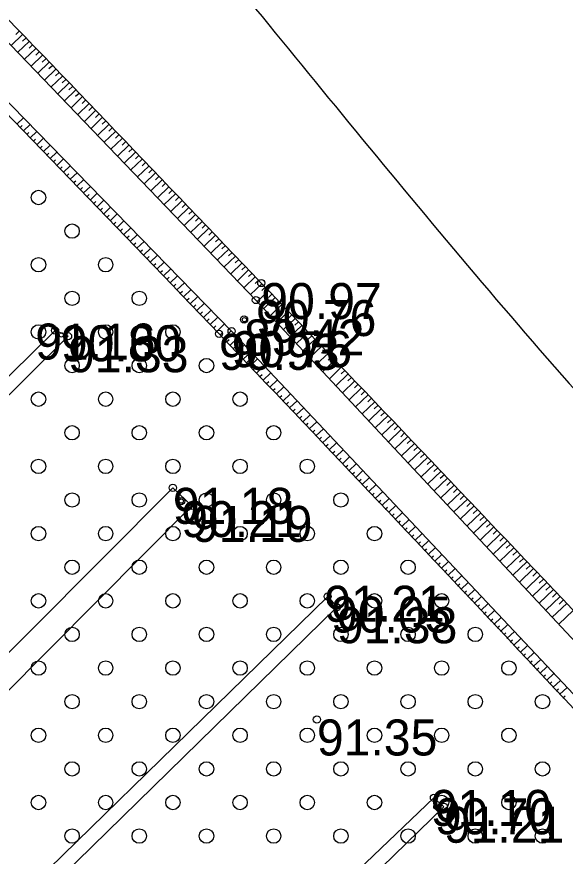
# Model space of a CAD drawing. Extents: x 316000 to 728450, y 314368 to 726000.
# Drawn here: x 725911.7 to 725968.9, y 315372.4 to 315459.8 of the extents above; entities that cross this region are included whole.
import ezdxf

# ---------------------------------------------------------------- set-up
doc = ezdxf.new("R2010")
doc.units = 0
for name, color, linetype in [('HIDG_ELEM_####_####_#', 7, 'Continuous'), ('HIDG_GRAV_####_####_#', 7, 'Continuous'), ('RELJ_AATZ_####_TKST_#', 7, 'Continuous'), ('RELJ_ELEM_####_####_#', 7, 'Continuous'), ('RELJ_HORZ_PAMT_####_#', 7, 'Continuous'), ('RELJ_NOGA_####_####_#', 7, 'Continuous'), ('TERT_ELEM_####_####_#', 7, 'Continuous')]:
    doc.layers.add(name, color=color, linetype=linetype)

msp = doc.modelspace()

# ---------------------------------------------------------------- linework, layer by layer
at = {"layer": 'HIDG_ELEM_####_####_#'}
for centre in [(725935.445, 315428.263), (725916.379, 315426.689), (725928.87, 315409.384), (725944.376, 315398.824), (725955.39, 315377.546)]:
    msp.add_circle(centre, 0.225, dxfattribs=at)
at = {"layer": 'HIDG_GRAV_####_####_#'}
for points in [[(726259.175, 315086.515), (726260.768, 315088.859), (726179.005, 315175.766), (726127.859, 315229.056), (726063.055, 315296.073), (725998.338, 315364.317), (725936.648, 315430.32), (725875.345, 315494.083), (725809.436, 315562.192), (725743.944, 315631.872)], [(725741.161, 315628.109), (725806.062, 315558.993), (725870.895, 315491.871), (725934.12, 315427.077), (725995.775, 315361.632), (726059.846, 315293.396), (726126.03, 315226.728), (726194.491, 315154.86), (726259.175, 315086.515)], [(725738.04, 315252.213), (725739.749, 315250.831), (725917.078, 315426.552), (725915.721, 315427.141), (725738.04, 315252.213)], [(725927.989, 315410.766), (725929.989, 315408.885), (725850.785, 315329.182), (725850.792, 315329.17), (725757.22, 315237.636), (725756.413, 315238.371), (725756.347, 315238.429), (725927.989, 315410.766)], [(725944.123, 315399.451), (725945.082, 315398.332), (725768.124, 315225.339), (725766.926, 315226.564), (725944.123, 315399.451)], [(725955.193, 315378.49), (725956.226, 315377.559), (725782.603, 315208.688), (725780.552, 315211.672), (725955.193, 315378.49)]]:
    msp.add_lwpolyline(points, dxfattribs=at)
at = {"layer": 'RELJ_ELEM_####_####_#'}
for centre in [(725937.206, 315432.091), (725936.648, 315430.32), (725935.41, 315428.298), (725915.721, 315427.141), (725934.12, 315427.077), (725917.078, 315426.552), (725932.803, 315426.796), (725927.989, 315410.766), (725928.87, 315409.384), (725929.989, 315408.885), (725944.123, 315399.451), (725945.082, 315398.332), (725943, 315386.643), (725955.193, 315378.49), (725956.226, 315377.559)]:
    msp.add_circle(centre, 0.375, dxfattribs=at)
at = {"layer": 'RELJ_HORZ_PAMT_####_#'}
msp.add_spline([(726116.344, 315699.088), (726105.94, 315702.687), (726040.128, 315715), (725990.823, 315710.424), (725942.032, 315708.248), (725920.28, 315706.773), (725880.366, 315714.514), (725859.054, 315708.681), (725859.054, 315672.662), (725851.263, 315613.969), (725853.471, 315568.895), (725840.997, 315555.788), (725885.558, 315509.629), (725935.943, 315461.491), (725983.423, 315406.25), (726032.861, 315360.511), (726082.852, 315311.191), (726122.235, 315248.757), (726137.049, 315229.286), (726180.187, 315183.1), (726194.517, 315168.27), (726211.91, 315146.926), (726212.513, 315143.157)], degree=3, dxfattribs=at)
at = {"layer": 'RELJ_NOGA_####_####_#'}
for p, q in [((725911.974, 315458.323), (725911.624, 315457.986)), ((725912.321, 315457.963), (725911.153, 315456.838)), ((725913.015, 315457.243), (725911.846, 315456.117)), ((725912.668, 315457.603), (725912.318, 315457.266)), ((725913.709, 315456.523), (725912.539, 315455.396)), ((725913.362, 315456.883), (725913.011, 315456.545)), ((725914.403, 315455.803), (725913.232, 315454.675)), ((725914.056, 315456.163), (725913.705, 315455.825)), ((725914.75, 315455.443), (725914.399, 315455.105)), ((725915.097, 315455.083), (725913.925, 315453.955)), ((725915.444, 315454.723), (725915.092, 315454.384)), ((725915.791, 315454.363), (725914.618, 315453.234)), ((725916.137, 315454.003), (725915.786, 315453.664)), ((725916.484, 315453.643), (725915.311, 315452.513)), ((725917.178, 315452.923), (725916.004, 315451.792)), ((725916.831, 315453.283), (725916.479, 315452.944)), ((725917.872, 315452.202), (725916.697, 315451.071)), ((725917.525, 315452.562), (725917.173, 315452.223)), ((725918.565, 315451.482), (725917.39, 315450.35)), ((725918.219, 315451.842), (725917.866, 315451.503)), ((725918.912, 315451.122), (725918.56, 315450.782)), ((725919.259, 315450.762), (725918.083, 315449.63)), ((725919.606, 315450.402), (725919.253, 315450.062)), ((725911.748, 315448.652), (725912.426, 315449.31)), ((725919.953, 315450.041), (725918.776, 315448.909)), ((725920.646, 315449.321), (725919.469, 315448.188)), ((725920.299, 315449.681), (725919.946, 315449.341)), ((725912.097, 315448.293), (725912.3, 315448.491)), ((725912.445, 315447.934), (725913.124, 315448.594)), ((725921.34, 315448.6), (725920.162, 315447.467)), ((725920.993, 315448.961), (725920.64, 315448.621)), ((725912.793, 315447.576), (725912.997, 315447.774)), ((725913.141, 315447.217), (725913.823, 315447.878)), ((725922.033, 315447.88), (725920.855, 315446.747)), ((725921.686, 315448.24), (725921.333, 315447.9)), ((725913.489, 315446.858), (725913.694, 315447.056)), ((725913.837, 315446.499), (725914.521, 315447.162)), ((725922.727, 315447.159), (725921.548, 315446.026)), ((725922.38, 315447.52), (725922.026, 315447.18)), ((725923.073, 315446.799), (725922.72, 315446.459)), ((725914.185, 315446.14), (725914.391, 315446.339)), ((725914.533, 315445.781), (725915.22, 315446.446)), ((725923.42, 315446.439), (725922.241, 315445.305)), ((725923.767, 315446.079), (725923.413, 315445.738)), ((725914.881, 315445.421), (725915.087, 315445.621)), ((725915.229, 315445.062), (725915.918, 315445.73)), ((725915.924, 315444.344), (725916.617, 315445.014)), ((725924.113, 315445.718), (725922.934, 315444.584)), ((725924.807, 315444.998), (725923.627, 315443.863)), ((725924.46, 315445.358), (725924.106, 315445.018)), ((725915.577, 315444.703), (725915.784, 315444.904)), ((725916.272, 315443.985), (725916.48, 315444.186)), ((725916.62, 315443.625), (725917.315, 315444.299)), ((725925.5, 315444.277), (725924.32, 315443.143)), ((725925.153, 315444.637), (725924.799, 315444.297)), ((725916.968, 315443.266), (725917.177, 315443.468)), ((725917.315, 315442.907), (725918.014, 315443.583)), ((725926.193, 315443.556), (725925.013, 315442.422)), ((725925.846, 315443.916), (725925.492, 315443.576)), ((725926.539, 315443.196), (725926.186, 315442.855)), ((725917.663, 315442.547), (725917.873, 315442.751)), ((725918.01, 315442.188), (725918.713, 315442.867)), ((725926.886, 315442.835), (725925.706, 315441.701)), ((725927.233, 315442.475), (725926.879, 315442.134)), ((725918.358, 315441.828), (725918.569, 315442.032)), ((725918.705, 315441.469), (725919.411, 315442.151)), ((725927.579, 315442.114), (725926.399, 315440.98)), ((725927.926, 315441.754), (725927.572, 315441.414)), ((725919.053, 315441.109), (725919.265, 315441.314)), ((725919.4, 315440.75), (725920.11, 315441.435)), ((725919.748, 315440.39), (725919.961, 315440.596)), ((725920.095, 315440.03), (725920.808, 315440.719)), ((725928.272, 315441.394), (725927.092, 315440.259)), ((725928.965, 315440.673), (725927.785, 315439.538)), ((725928.619, 315441.033), (725928.265, 315440.693)), ((725920.442, 315439.67), (725920.657, 315439.878)), ((725920.789, 315439.311), (725921.507, 315440.003)), ((725929.658, 315439.952), (725928.478, 315438.818)), ((725929.312, 315440.312), (725928.958, 315439.972)), ((725921.136, 315438.951), (725921.352, 315439.159)), ((725921.484, 315438.591), (725922.206, 315439.287)), ((725930.351, 315439.231), (725929.171, 315438.097)), ((725930.005, 315439.591), (725929.651, 315439.251)), ((725930.697, 315438.87), (725930.344, 315438.53)), ((725921.831, 315438.231), (725922.048, 315438.44)), ((725922.178, 315437.871), (725922.904, 315438.571)), ((725931.044, 315438.509), (725929.864, 315437.376)), ((725931.39, 315438.149), (725931.036, 315437.809)), ((725922.525, 315437.511), (725922.743, 315437.722)), ((725922.872, 315437.151), (725923.603, 315437.855)), ((725923.565, 315436.431), (725924.301, 315437.139)), ((725931.737, 315437.788), (725930.557, 315436.655)), ((725932.429, 315437.067), (725931.25, 315435.935)), ((725932.083, 315437.428), (725931.729, 315437.088)), ((725923.218, 315436.791), (725923.438, 315437.003)), ((725923.912, 315436.071), (725924.134, 315436.284)), ((725924.259, 315435.71), (725925, 315436.423)), ((725933.122, 315436.346), (725931.943, 315435.214)), ((725932.776, 315436.706), (725932.422, 315436.367)), ((725924.605, 315435.35), (725924.828, 315435.565)), ((725924.952, 315434.99), (725925.698, 315435.708)), ((725933.815, 315435.625), (725932.636, 315434.493)), ((725933.468, 315435.985), (725933.115, 315435.646)), ((725925.299, 315434.629), (725925.523, 315434.845)), ((725925.645, 315434.269), (725926.397, 315434.992)), ((725934.507, 315434.903), (725933.329, 315433.772)), ((725934.161, 315435.264), (725933.807, 315434.924)), ((725934.853, 315434.542), (725934.5, 315434.203)), ((725925.992, 315433.908), (725926.218, 315434.126)), ((725926.338, 315433.548), (725927.096, 315434.276)), ((725935.2, 315434.182), (725934.022, 315433.051)), ((725935.546, 315433.821), (725935.193, 315433.482)), ((725926.684, 315433.187), (725926.912, 315433.406)), ((725927.03, 315432.826), (725927.795, 315433.559)), ((725927.723, 315432.105), (725928.493, 315432.844)), ((725935.892, 315433.46), (725934.715, 315432.331)), ((725936.584, 315432.739), (725935.408, 315431.61)), ((725936.238, 315433.099), (725935.885, 315432.761)), ((725927.377, 315432.465), (725927.607, 315432.686)), ((725928.069, 315431.744), (725928.301, 315431.966)), ((725928.415, 315431.383), (725929.192, 315432.127)), ((725937.277, 315432.017), (725936.101, 315430.889)), ((725936.931, 315432.378), (725936.578, 315432.039)), ((725928.761, 315431.022), (725928.995, 315431.246)), ((725929.107, 315430.661), (725929.89, 315431.412)), ((725937.969, 315431.295), (725936.792, 315430.166)), ((725937.623, 315431.656), (725937.27, 315431.318)), ((725929.453, 315430.3), (725929.689, 315430.526)), ((725929.799, 315429.939), (725930.589, 315430.696)), ((725938.661, 315430.574), (725937.475, 315429.436)), ((725938.315, 315430.934), (725937.96, 315430.594)), ((725939.007, 315430.213), (725938.65, 315429.87)), ((725930.144, 315429.578), (725930.383, 315429.806)), ((725930.49, 315429.216), (725931.288, 315429.979)), ((725931.181, 315428.494), (725931.986, 315429.264)), ((725939.353, 315429.852), (725938.157, 315428.706)), ((725939.699, 315429.491), (725939.339, 315429.146)), ((725930.836, 315428.855), (725931.076, 315429.085)), ((725931.527, 315428.132), (725931.769, 315428.364)), ((725931.872, 315427.771), (725932.685, 315428.547)), ((725940.045, 315429.13), (725938.84, 315427.975)), ((725940.737, 315428.408), (725939.523, 315427.244)), ((725940.391, 315428.769), (725940.028, 315428.421)), ((725932.217, 315427.409), (725932.463, 315427.643)), ((725932.563, 315427.048), (725933.384, 315427.832)), ((725941.429, 315427.685), (725940.205, 315426.514)), ((725941.083, 315428.047), (725940.717, 315427.696)), ((725932.908, 315426.686), (725933.156, 315426.922)), ((725933.253, 315426.324), (725934.083, 315427.115)), ((725942.12, 315426.963), (725940.888, 315425.783)), ((725941.774, 315427.324), (725941.406, 315426.972)), ((725942.466, 315426.602), (725942.095, 315426.247)), ((725933.598, 315425.962), (725933.847, 315426.199)), ((725933.943, 315425.601), (725934.769, 315426.388)), ((725942.812, 315426.241), (725941.571, 315425.053)), ((725943.157, 315425.879), (725942.784, 315425.522)), ((725934.288, 315425.239), (725934.536, 315425.474)), ((725934.633, 315424.877), (725935.455, 315425.66)), ((725935.323, 315424.153), (725936.141, 315424.932)), ((725943.503, 315425.518), (725942.254, 315424.323)), ((725943.849, 315425.157), (725943.472, 315424.797)), ((725934.978, 315424.515), (725935.224, 315424.749)), ((725935.668, 315423.791), (725935.913, 315424.024)), ((725936.013, 315423.429), (725936.827, 315424.204)), ((725944.194, 315424.796), (725942.936, 315423.592)), ((725944.885, 315424.073), (725943.619, 315422.862)), ((725944.54, 315424.434), (725944.161, 315424.072)), ((725936.358, 315423.067), (725936.601, 315423.298)), ((725936.702, 315422.704), (725937.513, 315423.476)), ((725945.576, 315423.35), (725944.302, 315422.131)), ((725945.231, 315423.711), (725944.85, 315423.347)), ((725937.047, 315422.342), (725937.29, 315422.573)), ((725937.392, 315421.98), (725938.199, 315422.748)), ((725946.267, 315422.627), (725944.984, 315421.401)), ((725945.922, 315422.989), (725945.538, 315422.622)), ((725946.613, 315422.266), (725946.227, 315421.897)), ((725937.736, 315421.618), (725937.978, 315421.847)), ((725938.081, 315421.255), (725938.885, 315422.019)), ((725946.958, 315421.904), (725945.667, 315420.67)), ((725947.304, 315421.543), (725946.915, 315421.171)), ((725938.425, 315420.893), (725938.666, 315421.122)), ((725938.77, 315420.53), (725939.57, 315421.292)), ((725939.459, 315419.806), (725940.257, 315420.563)), ((725947.649, 315421.181), (725946.35, 315419.94)), ((725948.34, 315420.458), (725947.032, 315419.21)), ((725947.994, 315420.82), (725947.603, 315420.446)), ((725939.114, 315420.168), (725939.354, 315420.396)), ((725939.803, 315419.443), (725940.042, 315419.67)), ((725940.147, 315419.08), (725940.942, 315419.835)), ((725949.03, 315419.735), (725947.715, 315418.479)), ((725948.685, 315420.096), (725948.292, 315419.721)), ((725940.491, 315418.718), (725940.73, 315418.944)), ((725940.836, 315418.355), (725941.628, 315419.107)), ((725949.721, 315419.011), (725948.398, 315417.749)), ((725949.376, 315419.373), (725948.98, 315418.995)), ((725941.18, 315417.992), (725941.417, 315418.218)), ((725941.524, 315417.63), (725942.314, 315418.379)), ((725950.411, 315418.288), (725949.08, 315417.018)), ((725950.066, 315418.65), (725949.668, 315418.27)), ((725950.756, 315417.926), (725950.356, 315417.544)), ((725941.868, 315417.267), (725942.105, 315417.491)), ((725942.212, 315416.904), (725943, 315417.651)), ((725951.102, 315417.564), (725949.763, 315416.288)), ((725951.447, 315417.203), (725951.044, 315416.819)), ((725942.556, 315416.541), (725942.792, 315416.765)), ((725942.9, 315416.178), (725943.686, 315416.923)), ((725943.588, 315415.453), (725944.372, 315416.195)), ((725951.792, 315416.841), (725950.446, 315415.557)), ((725952.482, 315416.117), (725951.128, 315414.827)), ((725952.137, 315416.479), (725951.732, 315416.093)), ((725943.244, 315415.815), (725943.479, 315416.039)), ((725943.932, 315415.09), (725944.167, 315415.312)), ((725944.276, 315414.727), (725945.057, 315415.467)), ((725953.172, 315415.393), (725951.811, 315414.097)), ((725952.827, 315415.755), (725952.42, 315415.367)), ((725944.62, 315414.364), (725944.854, 315414.585)), ((725944.963, 315414), (725945.743, 315414.739)), ((725953.862, 315414.67), (725952.494, 315413.366)), ((725953.517, 315415.031), (725953.108, 315414.641)), ((725945.307, 315413.637), (725945.541, 315413.859)), ((725945.651, 315413.274), (725946.429, 315414.011)), ((725954.552, 315413.946), (725953.177, 315412.636)), ((725954.207, 315414.308), (725953.795, 315413.916)), ((725954.897, 315413.584), (725954.483, 315413.19)), ((725945.994, 315412.911), (725946.228, 315413.132)), ((725946.338, 315412.548), (725947.115, 315413.283)), ((725955.241, 315413.222), (725953.859, 315411.905)), ((725955.586, 315412.86), (725955.171, 315412.464)), ((725946.682, 315412.185), (725946.915, 315412.405)), ((725947.025, 315411.821), (725947.801, 315412.555)), ((725947.712, 315411.095), (725948.487, 315411.827)), ((725955.931, 315412.497), (725954.542, 315411.175)), ((725956.621, 315411.773), (725955.225, 315410.444)), ((725956.276, 315412.135), (725955.858, 315411.738)), ((725947.369, 315411.458), (725947.601, 315411.678)), ((725948.056, 315410.731), (725948.288, 315410.951)), ((725948.399, 315410.368), (725949.173, 315411.099)), ((725957.31, 315411.049), (725955.908, 315409.714)), ((725956.966, 315411.411), (725956.546, 315411.012)), ((725948.743, 315410.005), (725948.974, 315410.224)), ((725949.086, 315409.641), (725949.859, 315410.371)), ((725958, 315410.325), (725956.59, 315408.983)), ((725957.655, 315410.687), (725957.233, 315410.285)), ((725949.429, 315409.278), (725949.661, 315409.496)), ((725949.773, 315408.914), (725950.544, 315409.643)), ((725958.689, 315409.6), (725957.273, 315408.253)), ((725958.345, 315409.963), (725957.921, 315409.559)), ((725959.034, 315409.238), (725958.608, 315408.833)), ((725950.116, 315408.551), (725950.347, 315408.769)), ((725950.459, 315408.187), (725951.23, 315408.915)), ((725959.379, 315408.876), (725957.956, 315407.522)), ((725959.723, 315408.514), (725959.295, 315408.107)), ((725950.802, 315407.824), (725951.034, 315408.042)), ((725951.146, 315407.46), (725951.916, 315408.187)), ((725951.832, 315406.733), (725952.602, 315407.459)), ((725960.068, 315408.151), (725958.638, 315406.792)), ((725960.757, 315407.427), (725959.321, 315406.061)), ((725960.412, 315407.789), (725959.983, 315407.38)), ((725951.489, 315407.096), (725951.72, 315407.314)), ((725952.175, 315406.369), (725952.406, 315406.587)), ((725952.518, 315406.005), (725953.288, 315406.731)), ((725961.446, 315406.702), (725960.004, 315405.331)), ((725961.101, 315407.064), (725960.67, 315406.654)), ((725952.861, 315405.641), (725953.092, 315405.859)), ((725953.204, 315405.278), (725953.973, 315406.003)), ((725962.135, 315405.977), (725960.687, 315404.601)), ((725961.79, 315406.34), (725961.357, 315405.928)), ((725962.479, 315405.615), (725962.044, 315405.201)), ((725953.547, 315404.914), (725953.778, 315405.131)), ((725953.89, 315404.55), (725954.659, 315405.275)), ((725962.824, 315405.253), (725961.369, 315403.87)), ((725963.168, 315404.89), (725962.731, 315404.475)), ((725954.233, 315404.186), (725954.464, 315404.404)), ((725954.576, 315403.822), (725955.345, 315404.547)), ((725963.513, 315404.528), (725962.052, 315403.14)), ((725963.857, 315404.165), (725963.418, 315403.748)), ((725954.919, 315403.459), (725955.15, 315403.676)), ((725955.262, 315403.095), (725956.031, 315403.819)), ((725955.948, 315402.367), (725956.717, 315403.091)), ((725964.202, 315403.803), (725962.735, 315402.409)), ((725964.89, 315403.078), (725963.418, 315401.679)), ((725964.546, 315403.44), (725964.105, 315403.021)), ((725955.605, 315402.731), (725955.836, 315402.948)), ((725956.29, 315402.003), (725956.521, 315402.22)), ((725956.633, 315401.639), (725957.403, 315402.363)), ((725965.579, 315402.352), (725964.1, 315400.948)), ((725965.235, 315402.715), (725964.792, 315402.295)), ((725956.976, 315401.275), (725957.207, 315401.492)), ((725957.319, 315400.911), (725958.088, 315401.635)), ((725966.267, 315401.627), (725964.783, 315400.218)), ((725965.923, 315401.99), (725965.479, 315401.568)), ((725966.612, 315401.265), (725966.165, 315400.841)), ((725957.662, 315400.547), (725957.892, 315400.764)), ((725958.004, 315400.183), (725958.774, 315400.907)), ((725966.956, 315400.902), (725965.466, 315399.487)), ((725967.3, 315400.539), (725966.852, 315400.114)), ((725958.347, 315399.819), (725958.578, 315400.036)), ((725958.69, 315399.455), (725959.46, 315400.179)), ((725967.644, 315400.177), (725966.149, 315398.757)), ((725967.989, 315399.814), (725967.539, 315399.387)), ((725959.032, 315399.09), (725959.263, 315399.308)), ((725959.375, 315398.726), (725960.146, 315399.451)), ((725960.06, 315397.998), (725960.831, 315398.724)), ((725968.333, 315399.451), (725966.831, 315398.027)), ((725969.021, 315398.726), (725967.514, 315397.296)), ((725968.677, 315399.089), (725968.226, 315398.661)), ((725959.718, 315398.362), (725959.949, 315398.58)), ((725960.403, 315397.634), (725960.634, 315397.852)), ((725960.745, 315397.27), (725961.517, 315397.995)), ((725969.709, 315398.001), (725968.197, 315396.565)), ((725961.088, 315396.905), (725961.32, 315397.123)), ((725961.43, 315396.541), (725962.203, 315397.268)), ((725961.773, 315396.177), (725962.005, 315396.395)), ((725962.116, 315395.813), (725962.889, 315396.54)), ((725962.458, 315395.448), (725962.69, 315395.667)), ((725962.801, 315395.084), (725963.575, 315395.812)), ((725963.143, 315394.72), (725963.375, 315394.938)), ((725963.485, 315394.355), (725964.26, 315395.084)), ((725964.17, 315393.627), (725964.946, 315394.356)), ((725963.828, 315393.991), (725964.06, 315394.21)), ((725964.513, 315393.262), (725964.746, 315393.481)), ((725964.855, 315392.898), (725965.632, 315393.628)), ((725965.198, 315392.534), (725965.431, 315392.753)), ((725965.54, 315392.169), (725966.318, 315392.9)), ((725965.882, 315391.805), (725966.116, 315392.024)), ((725966.225, 315391.44), (725967.003, 315392.172)), ((725966.567, 315391.076), (725966.801, 315391.296)), ((725966.909, 315390.712), (725967.689, 315391.444)), ((725967.252, 315390.347), (725967.486, 315390.567)), ((725967.594, 315389.983), (725968.375, 315390.716)), ((725968.278, 315389.254), (725969.061, 315389.988)), ((725967.936, 315389.618), (725968.171, 315389.838)), ((725968.621, 315388.889), (725968.856, 315389.11))]:
    msp.add_line(p, q, dxfattribs=at)
for points in [[(726259.118, 315084.507), (726262.723, 315089.259), (726261.561, 315090.837), (726260.205, 315092.42), (726257.293, 315095.532), (726218.912, 315136.383), (726180.307, 315176.838), (726128.672, 315229.97), (726063.701, 315298.11), (725999.895, 315366.094), (725937.206, 315432.091), (725876.347, 315495.232), (725810.578, 315563.083), (725744.701, 315632.911)], [(725740.862, 315626.984), (725805.544, 315558.116), (725870.385, 315491.147), (725932.803, 315426.796), (725994.977, 315360.836), (726059.661, 315292.118), (726075.746, 315275.458), (726092.085, 315259.043), (726108.47, 315242.673), (726124.693, 315226.144), (726193.269, 315154.025), (726250.062, 315092.6), (726256.318, 315085.83), (726258.824, 315084.289), (726259.118, 315084.507)]]:
    msp.add_spline(points, degree=3, dxfattribs=at)
at = {"layer": 'TERT_ELEM_####_####_#'}
for centre in [(725914, 315441), (725917.5, 315437.5), (725914, 315434), (725921, 315434), (725917.5, 315430.5), (725924.5, 315430.5), (725914, 315427), (725921, 315427), (725928, 315427), (725917.5, 315423.5), (725924.5, 315423.5), (725931.5, 315423.5), (725914, 315420), (725921, 315420), (725928, 315420), (725935, 315420), (725917.5, 315416.5), (725924.5, 315416.5), (725931.5, 315416.5), (725938.5, 315416.5), (725914, 315413), (725921, 315413), (725928, 315413), (725935, 315413), (725942, 315413), (725917.5, 315409.5), (725924.5, 315409.5), (725931.5, 315409.5), (725938.5, 315409.5), (725945.5, 315409.5), (725914, 315406), (725921, 315406), (725928, 315406), (725935, 315406), (725942, 315406), (725949, 315406), (725917.5, 315402.5), (725924.5, 315402.5), (725931.5, 315402.5), (725938.5, 315402.5), (725945.5, 315402.5), (725952.5, 315402.5), (725914, 315399), (725921, 315399), (725928, 315399), (725935, 315399), (725942, 315399), (725949, 315399), (725956, 315399), (725917.5, 315395.5), (725924.5, 315395.5), (725931.5, 315395.5), (725938.5, 315395.5), (725945.5, 315395.5), (725952.5, 315395.5), (725959.5, 315395.5), (725914, 315392), (725921, 315392), (725928, 315392), (725935, 315392), (725942, 315392), (725949, 315392), (725956, 315392), (725963, 315392), (725917.5, 315388.5), (725924.5, 315388.5), (725931.5, 315388.5), (725938.5, 315388.5), (725945.5, 315388.5), (725952.5, 315388.5), (725959.5, 315388.5), (725966.5, 315388.5), (725914, 315385), (725921, 315385), (725928, 315385), (725935, 315385), (725942, 315385), (725949, 315385), (725956, 315385), (725963, 315385), (725917.5, 315381.5), (725924.5, 315381.5), (725931.5, 315381.5), (725938.5, 315381.5), (725945.5, 315381.5), (725952.5, 315381.5), (725959.5, 315381.5), (725966.5, 315381.5), (725914, 315378), (725921, 315378), (725928, 315378), (725935, 315378), (725942, 315378), (725949, 315378), (725956, 315378), (725963, 315378), (725917.5, 315374.5), (725924.5, 315374.5), (725931.5, 315374.5), (725938.5, 315374.5), (725945.5, 315374.5), (725952.5, 315374.5), (725959.5, 315374.5), (725966.5, 315374.5)]:
    msp.add_circle(centre, 0.75, dxfattribs=at)

# ---------------------------------------------------------------- texts
at = {"layer": 'RELJ_AATZ_####_TKST_#'}
for s, p in [('90.97', (725937.206, 315428.341)), ('90.76', (725936.648, 315426.57)), ('89.42', (725935.41, 315424.548)), ('91.16', (725913.657, 315424.122)), ('90.80', (725916.33, 315423.938)), ('91.33', (725917.078, 315422.802)), ('90.93', (725932.803, 315423.046)), ('90.76', (725934.12, 315423.327)), ('91.18', (725927.989, 315407.016)), ('90.21', (725928.87, 315405.634)), ('91.19', (725929.989, 315405.135)), ('91.21', (725943.765, 315396.82)), ('90.05', (725944.464, 315395.693)), ('91.38', (725945.082, 315394.582)), ('91.35', (725943, 315382.893)), ('91.10', (725954.859, 315375.56)), ('90.70', (725955.281, 315374.683)), ('91.21', (725956.226, 315373.809))]:
    msp.add_text(s, height=3.75, dxfattribs=at).set_placement(p)

doc.saveas('drawing.dxf')
